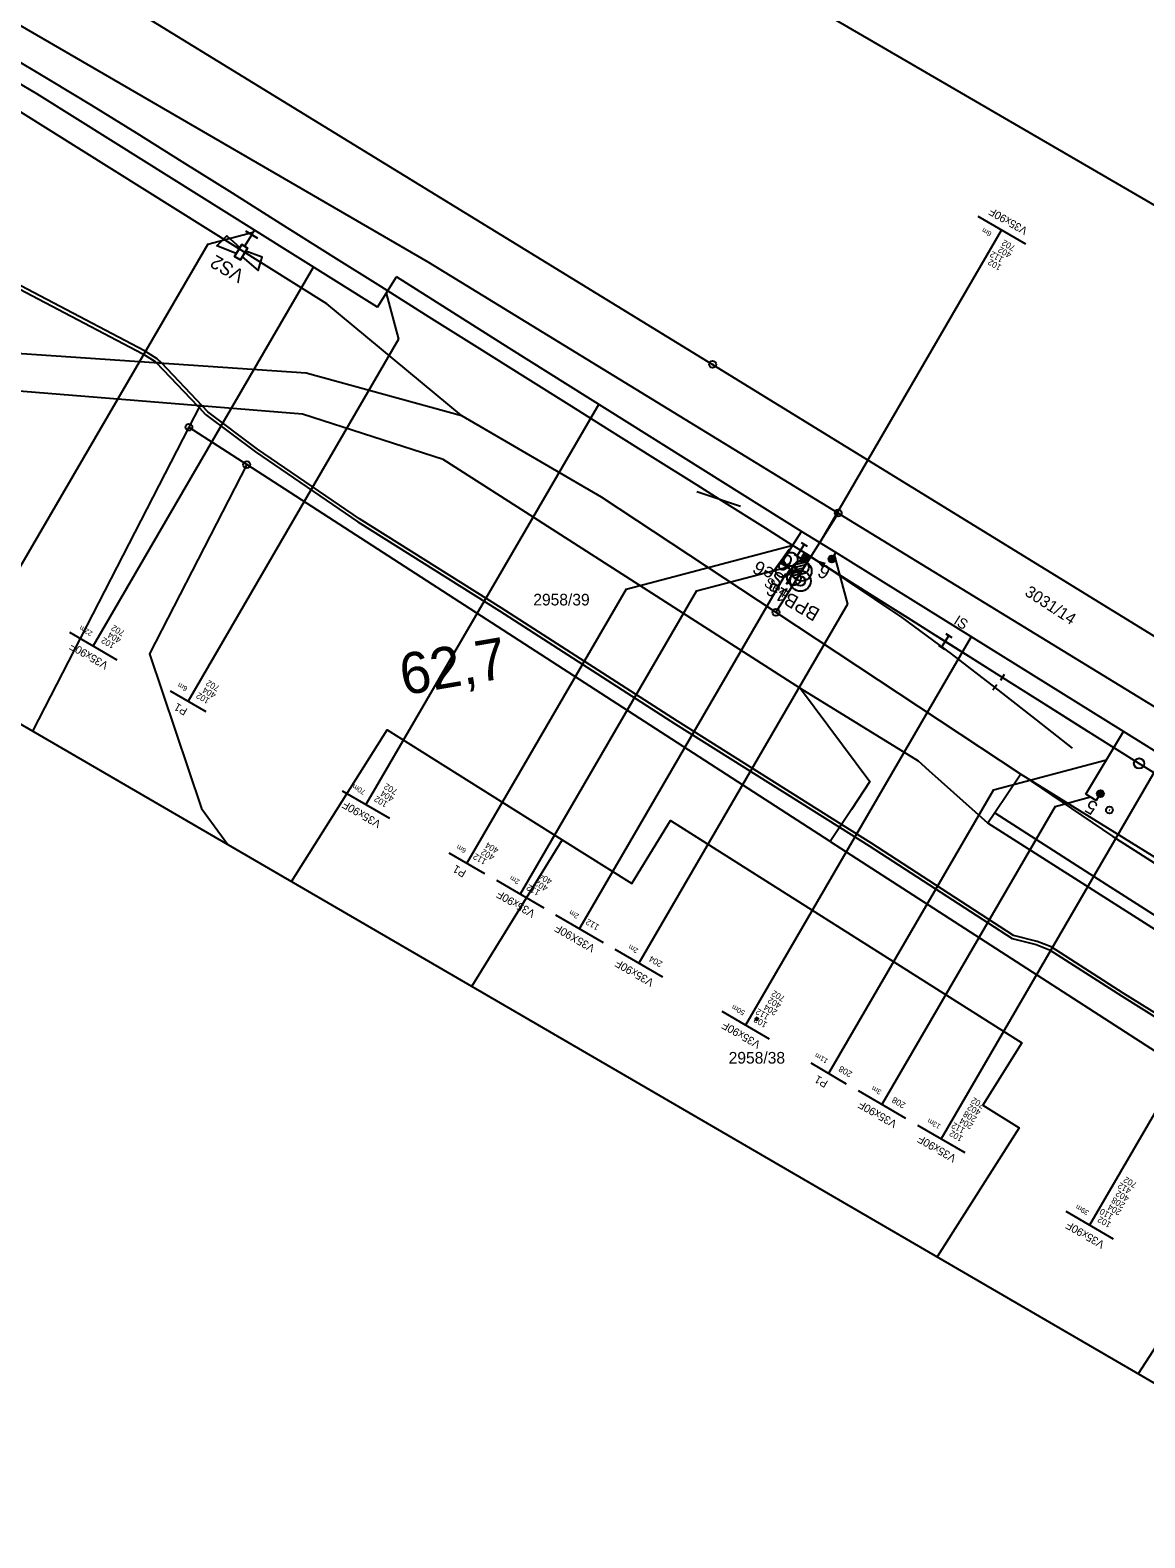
# Model space of a CAD drawing. Extents: x -621126 to -620688, y -1122470 to -1122131.
# Drawn here: x -620965.5 to -620803, y -1122470.1 to -1122250.2 of the extents above; entities that cross this region are included whole.
import ezdxf

# ---------------------------------------------------------------- set-up
doc = ezdxf.new("R2010")
doc.units = 0
for name, color, linetype in [('hm', 7, 'Continuous'), ('HranDP', 7, 'Continuous'), ('Hranice parcel', 7, 'Continuous'), ('Parcelní čísla', 7, 'Continuous'), ('Rámečky-tisk', 7, 'Continuous'), ('STANICENI NOVE HM', 7, 'Continuous'), ('Vnitřní kresba', 7, 'Continuous'), ('Vrstva 1', 7, 'Continuous'), ('Vrstva 2', 7, 'Continuous'), ('Vrstva 3', 7, 'Continuous'), ('Vrstva 33', 7, 'Continuous'), ('Vrstva 6', 7, 'Continuous'), ('Vrstva 7', 7, 'Continuous'), ('Věcná břemena k části', 7, 'Continuous'), ('Značky bodu BP', 7, 'Continuous'), ('Značky budov', 7, 'Continuous')]:
    doc.layers.add(name, color=color, linetype=linetype)

msp = doc.modelspace()

# ---------------------------------------------------------------- linework, layer by layer
at = {"layer": 'hm'}
for p, q in [((-620963.63, -1122256.97), (-620963.63, -1122256.97)), ((-620879.03, -1122309.95), (-620879.03, -1122309.95))]:
    msp.add_line(p, q, dxfattribs=at)
at = {"layer": 'HranDP'}
msp.add_line((-620856.79, -1122335.14), (-620821.12, -1122358.76), dxfattribs=at)
for points in [[(-620902.62, -1122306.44), (-620922.25, -1122290.14), (-620980.18, -1122253.91), (-621018.36, -1122232.1), (-621052.69, -1122216.23), (-621091.75, -1122200.22)], [(-620847.72, -1122320.67), (-620907.48, -1122284.08), (-620974.87, -1122244.96), (-620982.44, -1122240.65)], [(-620902.62, -1122306.44), (-620882.26, -1122318.28), (-620856.79, -1122335.14)], [(-620847.72, -1122320.67), (-620838.83, -1122326.12), (-620768.63, -1122369.09), (-620748.53, -1122378.52), (-620719.75, -1122396)], [(-620821.12, -1122358.76), (-620741.46, -1122408.09), (-620730.75, -1122414.92)]]:
    msp.add_lwpolyline(points, dxfattribs=at)
at = {"layer": 'Hranice parcel'}
for p, q in [((-620976.86, -1122231), (-620866.03, -1122298.98)), ((-620866.03, -1122298.98), (-620716.77, -1122390.88)), ((-620940.78, -1122305.04), (-620942.38, -1122308.15)), ((-620942.38, -1122308.15), (-620965.18, -1122352.45)), ((-620942.38, -1122308.15), (-620933.94, -1122313.6)), ((-620848.87, -1122368.55), (-620933.94, -1122313.6)), ((-620853.22, -1122346.25), (-620894.54, -1122319.77)), ((-620847.72, -1122320.67), (-620856.79, -1122335.14)), ((-620856.79, -1122335.14), (-620821.12, -1122358.76))]:
    msp.add_line(p, q, dxfattribs=at)
for points in [[(-620902.62, -1122306.44), (-620922.25, -1122290.14), (-620980.18, -1122253.91), (-621018.36, -1122232.1), (-621052.69, -1122216.23), (-621091.75, -1122200.22)], [(-620847.72, -1122320.67), (-620907.48, -1122284.08), (-620974.87, -1122244.96), (-620982.44, -1122240.65)], [(-621115.61, -1122241.25), (-621038.08, -1122280.28), (-621008.67, -1122291.25), (-620981.77, -1122296.39), (-620925.27, -1122300.21), (-620902.62, -1122306.44)], [(-620940.78, -1122305.04), (-620976.17, -1122302.17), (-620982.88, -1122301.63), (-621009.79, -1122296.2), (-621017.3, -1122293.74)], [(-620894.54, -1122319.77), (-620905.33, -1122312.86), (-620925.79, -1122306.26), (-620940.78, -1122305.04)], [(-620902.62, -1122306.44), (-620882.26, -1122318.28), (-620856.79, -1122335.14)], [(-620933.94, -1122313.6), (-620948.13, -1122341.18), (-620940.52, -1122363.74), (-620936.7, -1122369.01)], [(-620847.72, -1122320.67), (-620838.83, -1122326.12), (-620768.63, -1122369.09), (-620748.53, -1122378.52), (-620719.75, -1122396)], [(-620825.92, -1122365.89), (-620834.44, -1122358.28), (-620836.04, -1122356.85), (-620853.22, -1122346.25)], [(-620853.22, -1122346.25), (-620843.09, -1122359.81), (-620845.8, -1122363.88), (-620848.5, -1122367.99), (-620848.87, -1122368.55)], [(-620927.44, -1122374.39), (-620913.46, -1122352.29), (-620887.98, -1122368.3), (-620877.81, -1122374.71), (-620872.17, -1122365.51), (-620820.94, -1122397.9), (-620826.62, -1122407), (-620821.36, -1122410.31), (-620833.31, -1122429.13)], [(-620821.12, -1122358.76), (-620824.91, -1122364.39), (-620825.92, -1122365.89)], [(-620821.12, -1122358.76), (-620741.46, -1122408.09), (-620730.75, -1122414.92)], [(-620821.12, -1122358.76), (-620807.67, -1122367.84), (-620731.57, -1122416.33)], [(-620735.65, -1122423.34), (-620825.92, -1122365.89)], [(-620848.87, -1122368.55), (-620781.81, -1122411.87), (-620803.98, -1122446.19)]]:
    msp.add_lwpolyline(points, dxfattribs=at)
at = {"layer": 'Rámečky-tisk'}
for points in [[(-621051.28, -1122130.61), (-621125.92, -1122258.99), (-620762.84, -1122470.11)], [(-620762.84, -1122470.11), (-620688.19, -1122341.73), (-621051.28, -1122130.61)]]:
    msp.add_lwpolyline(points, dxfattribs=at)
at = {"layer": 'Vnitřní kresba'}
for p, q in [((-620824.91, -1122364.39), (-620810.36, -1122373.73)), ((-620887.98, -1122368.3), (-620901.15, -1122389.68)), ((-620810.36, -1122373.73), (-620734.88, -1122422.02))]:
    msp.add_line(p, q, dxfattribs=at)
at = {"layer": 'Vrstva 1'}
for p, q in [((-620933.22, -1122280.07), (-620932.81, -1122279.39)), ((-620914.88, -1122290.62), (-620932.81, -1122279.39)), ((-620914.88, -1122290.62), (-620912.11, -1122286.23)), ((-620856.02, -1122328.01), (-620853.07, -1122323.34)), ((-620848.09, -1122326.43), (-620853.07, -1122323.34)), ((-620806.11, -1122352.53), (-620848.09, -1122326.43)), ((-620856.02, -1122328.01), (-620854.72, -1122328.89)), ((-620811.62, -1122361.65), (-620806.11, -1122352.53))]:
    msp.add_line(p, q, dxfattribs=at)
for points in [[(-620932.81, -1122279.39), (-620953.35, -1122266.52), (-620964.54, -1122259.53), (-620979.4, -1122250.79), (-620982.11, -1122249.22), (-620983.24, -1122251.5), (-620999.51, -1122242.21), (-621017.63, -1122231.73), (-621018.87, -1122231.17), (-621038.19, -1122222.46)], [(-620969.11, -1122253.64), (-620962.44, -1122257.63), (-620956.58, -1122261.19), (-620949.96, -1122265.28), (-620943.39, -1122269.38), (-620936.05, -1122273.98), (-620929.02, -1122278.42), (-620921.28, -1122283.3), (-620914.45, -1122287.58), (-620907.38, -1122292.04), (-620900.38, -1122296.43), (-620893.37, -1122300.83), (-620887.01, -1122304.84), (-620881.07, -1122308.56), (-620874.8, -1122312.5), (-620868.33, -1122316.57), (-620865.13, -1122318.58), (-620858.38, -1122322.84), (-620854.48, -1122325.28), (-620853.21, -1122326.08), (-620851.73, -1122327.01), (-620850.55, -1122327.76), (-620840.58, -1122334.05), (-620833.63, -1122338.43), (-620832.14, -1122339.37), (-620823.78, -1122344.63), (-620817.74, -1122348.46), (-620811.37, -1122352.45)], [(-620853.07, -1122323.34), (-620895.69, -1122296.63), (-620912.11, -1122286.23)], [(-620848.09, -1122326.43), (-620848.09, -1122326.43), (-620848.63, -1122327.36)], [(-620851.64, -1122327.08), (-620843.14, -1122332.43), (-620837.63, -1122335.92), (-620832.12, -1122339.39), (-620828.02, -1122341.97), (-620823.79, -1122344.63), (-620816.97, -1122348.94), (-620810.35, -1122353.09), (-620803.86, -1122357.18), (-620803.36, -1122357.5), (-620800.13, -1122359.53), (-620798.65, -1122360.46), (-620794.42, -1122363.12), (-620788.1, -1122367.1), (-620781.12, -1122371.5), (-620774.17, -1122375.88), (-620767.51, -1122380.06), (-620763.22, -1122382.76), (-620756.39, -1122387.05), (-620748.87, -1122391.78), (-620741.59, -1122396.35), (-620734.61, -1122400.75), (-620727.79, -1122405.03), (-620725.75, -1122406.32)], [(-620850.55, -1122327.76), (-620838.47, -1122335.9), (-620831.26, -1122341.18), (-620824.88, -1122346.1), (-620819.56, -1122350.3), (-620813.61, -1122354.97)], [(-620854.72, -1122328.89), (-620855.09, -1122329.44), (-620854.51, -1122329.81)], [(-620795.27, -1122359.26), (-620795.68, -1122359.01), (-620806.11, -1122352.53)], [(-620809.51, -1122361.58), (-620810.11, -1122362.57), (-620811.62, -1122361.65)]]:
    msp.add_lwpolyline(points, dxfattribs=at)
at = {"layer": 'Vrstva 2'}
for p, q in [((-620934.25, -1122281.78), (-620933.22, -1122280.07)), ((-620934.25, -1122281.78), (-620933.22, -1122280.07)), ((-620932.37, -1122280.58), (-620934.08, -1122279.55)), ((-620934.08, -1122279.55), (-620932.37, -1122280.58)), ((-620853.74, -1122328.53), (-620855.29, -1122331.09)), ((-620852.5, -1122328.24), (-620854.45, -1122328.69)), ((-620852.38, -1122327.83), (-620854.23, -1122328.25)), ((-620852.28, -1122327.88), (-620853.83, -1122330.36)), ((-620853.2, -1122327.4), (-620851.84, -1122327.07)), ((-620853.13, -1122327.52), (-620851.85, -1122327.21)), ((-620853.1, -1122327.25), (-620852, -1122326.97)), ((-620853.01, -1122327.09), (-620852.16, -1122326.88)), ((-620852.97, -1122327.62), (-620851.95, -1122327.37)), ((-620852.91, -1122326.93), (-620852.32, -1122326.78)), ((-620852.82, -1122326.77), (-620852.48, -1122326.69)), ((-620852.81, -1122327.71), (-620852.05, -1122327.52)), ((-620852.72, -1122326.61), (-620852.64, -1122326.59)), ((-620852.65, -1122327.81), (-620852.14, -1122327.68)), ((-620852.49, -1122327.91), (-620852.24, -1122327.84)), ((-620852.28, -1122327.88), (-620851.73, -1122327.01)), ((-620852.28, -1122327.88), (-620852.28, -1122327.88)), ((-620848.14, -1122327.31), (-620849.13, -1122327.42)), ((-620848.2, -1122327.11), (-620849.11, -1122327.21)), ((-620848.16, -1122327.51), (-620849.07, -1122327.61)), ((-620848.38, -1122326.93), (-620848.97, -1122327)), ((-620848.29, -1122327.73), (-620848.88, -1122327.79)), ((-620852.78, -1122328.69), (-620854.51, -1122329.09)), ((-620853.07, -1122329.14), (-620854.47, -1122329.46)), ((-620853.35, -1122329.59), (-620854.34, -1122329.82)), ((-620853.63, -1122330.04), (-620854.09, -1122330.15)), ((-620824.58, -1122345.71), (-620825.19, -1122346.5)), ((-620823.51, -1122344.21), (-620824.04, -1122345.06)), ((-620809.97, -1122361.38), (-620809.83, -1122361.96)), ((-620809.82, -1122361.18), (-620809.6, -1122362.07)), ((-620809.63, -1122361.09), (-620809.39, -1122362.06)), ((-620809.43, -1122361.09), (-620809.21, -1122361.97)), ((-620809.2, -1122361.19), (-620809.05, -1122361.77))]:
    msp.add_line(p, q, dxfattribs=at)
for points in [[(-620935.46, -1122282.8), (-620938.28, -1122281.68), (-620936.82, -1122280.23), (-620934.94, -1122281.95)], [(-620934.86, -1122283.75), (-620935.72, -1122283.23), (-620934.68, -1122281.52), (-620933.83, -1122282.04)], [(-620935.72, -1122283.23), (-620934.86, -1122283.75), (-620933.83, -1122282.04), (-620934.68, -1122281.52)], [(-620934.6, -1122283.32), (-620932.29, -1122285.3), (-620931.69, -1122283.33), (-620934.08, -1122282.46)], [(-620852.69, -1122326.56), (-620851.79, -1122327.1), (-620852.33, -1122328), (-620853.23, -1122327.46)], [(-620852.69, -1122326.56), (-620851.79, -1122327.1), (-620852.33, -1122328), (-620853.23, -1122327.46)]]:
    msp.add_lwpolyline(points, close=True, dxfattribs=at)
msp.add_lwpolyline([(-620849.6, -1122328.08), (-620850.55, -1122327.76), (-620849.89, -1122328.51)], dxfattribs=at)
for centre, radius in [((-620853.06, -1122329.13), 1.46), ((-620848.63, -1122327.36), 0.5), ((-620853.23, -1122330.58), 1.5), ((-620853.23, -1122330.58), 0.7), ((-620809.51, -1122361.58), 0.5)]:
    msp.add_circle(centre, radius, dxfattribs=at)
msp.add_arc((-620853.05, -1122329.12), 1.46, 57.9828, 237.9436, dxfattribs=at)
at = {"layer": 'Vrstva 3'}
for p, q in [((-620868.31, -1122317.51), (-620861.96, -1122319.66)), ((-620852.68, -1122325.24), (-620853.74, -1122326.93)), ((-620853.1, -1122324.97), (-620852.25, -1122325.5)), ((-620854.16, -1122326.67), (-620853.32, -1122327.2)), ((-620831.61, -1122338.52), (-620832.67, -1122340.21)), ((-620831.58, -1122338.54), (-620832.65, -1122340.24)), ((-620832.03, -1122338.25), (-620831.18, -1122338.79)), ((-620832.01, -1122338.28), (-620831.16, -1122338.81)), ((-620833.1, -1122339.95), (-620832.25, -1122340.48)), ((-620833.07, -1122339.97), (-620832.22, -1122340.5))]:
    msp.add_line(p, q, dxfattribs=at)
at = {"layer": 'Vrstva 33'}
for p, q in [((-620827.36, -1122277.38), (-620820.44, -1122281.4)), ((-620939.61, -1122281.44), (-620932.99, -1122279.69)), ((-620850.42, -1122324.99), (-620823.9, -1122279.39)), ((-620939.61, -1122281.44), (-620969.3, -1122332.5)), ((-620924.2, -1122284.78), (-620956.33, -1122340.04)), ((-620913.61, -1122288.6), (-620911.83, -1122295.33)), ((-620911.83, -1122295.33), (-620942.5, -1122348.08)), ((-620882.64, -1122304.81), (-620916.57, -1122363.16)), ((-620878.65, -1122331.77), (-620854.32, -1122325.33)), ((-620868.39, -1122332.03), (-620855.22, -1122328.55)), ((-620848.29, -1122326.76), (-620846.38, -1122333.97)), ((-620855.41, -1122329.6), (-620885.45, -1122381.26)), ((-620855.41, -1122329.6), (-620855.01, -1122329.5)), ((-620878.65, -1122331.77), (-620901.87, -1122371.71)), ((-620868.39, -1122332.03), (-620894.09, -1122376.23)), ((-620846.38, -1122333.97), (-620876.8, -1122386.29)), ((-620959.79, -1122338.03), (-620952.88, -1122342.05)), ((-620828.32, -1122338.72), (-620861.24, -1122395.33)), ((-620945.1, -1122346.58), (-620939.91, -1122349.59)), ((-620800.28, -1122356.14), (-620832.72, -1122411.92)), ((-620825.1, -1122361.03), (-620808.6, -1122356.67)), ((-620920.03, -1122361.15), (-620913.11, -1122365.17)), ((-620825.1, -1122361.03), (-620849.14, -1122402.37)), ((-620816.09, -1122363.44), (-620841.36, -1122406.9)), ((-620816.09, -1122363.44), (-620810.93, -1122362.07)), ((-620904.47, -1122370.2), (-620899.28, -1122373.22)), ((-620779.04, -1122369.35), (-620811.1, -1122424.49)), ((-620897.55, -1122374.22), (-620890.63, -1122378.24)), ((-620888.91, -1122379.25), (-620881.99, -1122383.27)), ((-620880.26, -1122384.28), (-620873.34, -1122388.3)), ((-620864.7, -1122393.32), (-620857.78, -1122397.34)), ((-620851.73, -1122400.86), (-620846.55, -1122403.88)), ((-620844.82, -1122404.88), (-620837.9, -1122408.91)), ((-620836.18, -1122409.91), (-620829.26, -1122413.93)), ((-620814.56, -1122422.48), (-620807.64, -1122426.5))]:
    msp.add_line(p, q, dxfattribs=at)
at = {"layer": 'Vrstva 6'}
for p, q in [((-620854.88, -1122326), (-620856.04, -1122327.63)), ((-620856.04, -1122327.63), (-620857.21, -1122329.26))]:
    msp.add_line(p, q, dxfattribs=at)
for centre in [(-620854.65, -1122327.4), (-620855.81, -1122329.03), (-620853.02, -1122328.56), (-620854.18, -1122330.19)]:
    msp.add_ellipse(centre, major_axis=(0.814, -0.582), ratio=0.999505, dxfattribs=at)
at = {"layer": 'Vrstva 7'}
msp.add_line((-620808.23, -1122363.94), (-620808.14, -1122363.99), dxfattribs=at)
for centre, radius in [((-620803.86, -1122357.18), 0.75), ((-620808.18, -1122363.97), 0.5)]:
    msp.add_circle(centre, radius, dxfattribs=at)
at = {"layer": 'Věcná břemena k části'}
for points in [[(-621104.33, -1122221.85), (-621094.36, -1122225.8), (-621066.48, -1122237.54), (-621033.9, -1122251.82), (-621004.33, -1122267.35), (-620977.59, -1122282.48), (-620949.07, -1122297.45), (-620947.3, -1122298.56), (-620947.13, -1122298.73), (-620946.39, -1122298.78), (-620946.98, -1122298.16), (-620948.83, -1122297.01), (-620977.35, -1122282.04), (-621004.09, -1122266.91), (-621033.68, -1122251.36), (-621066.28, -1122237.08), (-621094.18, -1122225.34), (-621104.08, -1122221.42)], [(-620794.67, -1122397.82), (-620806.18, -1122390.67), (-620816.7, -1122383.9), (-620818.72, -1122383.12), (-620822.15, -1122382.27), (-620842.97, -1122368.76), (-620847.24, -1122366.07), (-620847.51, -1122366.48), (-620843.23, -1122369.18), (-620822.35, -1122382.73), (-620818.88, -1122383.6), (-620816.92, -1122384.34), (-620806.44, -1122391.09), (-620794.95, -1122398.24)]]:
    msp.add_lwpolyline(points, dxfattribs=at)
for points in [[(-620941.14, -1122305.01), (-620940.4, -1122305.07), (-620946.39, -1122298.78), (-620947.13, -1122298.73)], [(-620940.9, -1122305.27), (-620939.94, -1122306.28), (-620932.68, -1122311.73), (-620917.76, -1122321.94), (-620897.11, -1122334.91), (-620871.42, -1122351.43), (-620847.51, -1122366.48), (-620847.24, -1122366.07), (-620871.16, -1122351.01), (-620896.85, -1122334.49), (-620917.48, -1122321.52), (-620932.38, -1122311.33), (-620939.6, -1122305.9), (-620940.4, -1122305.07), (-620940.78, -1122305.04)]]:
    msp.add_lwpolyline(points, close=True, dxfattribs=at)
at = {"layer": 'Značky bodu BP'}
for centre, radius in [((-620866.03, -1122298.98), 0.5), ((-620866.03, -1122298.98), 0.0303), ((-620942.38, -1122308.15), 0.5), ((-620942.38, -1122308.15), 0.0303), ((-620933.94, -1122313.6), 0.5), ((-620933.94, -1122313.6), 0.0303), ((-620847.72, -1122320.67), 0.5), ((-620847.72, -1122320.67), 0.0303), ((-620856.79, -1122335.14), 0.5), ((-620856.79, -1122335.14), 0.0303)]:
    msp.add_circle(centre, radius, dxfattribs=at)
at = {"layer": 'Značky budov'}
msp.add_circle((-620859.61, -1122394.47), 0.175, dxfattribs=at)

# ---------------------------------------------------------------- texts
at = {"layer": 'Parcelní čísla'}
for s, p in [('2958/39', (-620892.17, -1122334.14)), ('2958/38', (-620863.69, -1122400.95))]:
    msp.add_text(s, height=1.7, dxfattribs=at).set_placement(p)
msp.add_text('3031/14', height=1.7, rotation=327, dxfattribs=at).set_placement((-620820.66, -1122332.56))
at = {"layer": 'STANICENI NOVE HM'}
msp.add_text('62,7', height=6, rotation=9.6991, dxfattribs=at).set_placement((-620911.08, -1122347.26))
at = {"layer": 'Vrstva 2'}
msp.add_text('6', height=2.5, rotation=147.9632, dxfattribs=at).set_placement((-620853.99, -1122327.35))
at = {"layer": 'Vrstva 3'}
for s, height, rotation, p in [('VS2', 2, 149.8236, (-620934.1, -1122285.47)), ('Se6', 2, 149.8236, (-620855.28, -1122329.88)), ('6', 2, 149.8236, (-620848.64, -1122328.75)), ('BPB16', 2, 149.8236, (-620850.23, -1122334.81)), ('IS', 1.5, 327.8592, (-620831.01, -1122336.74)), ('5', 2, 148.8786, (-620809.69, -1122363.11))]:
    msp.add_text(s, height=height, rotation=rotation, dxfattribs=at).set_placement(p)
at = {"layer": 'Vrstva 33'}
for s, height, p in [('V35x90F', 1.15, (-620820.01, -1122279.17)), ('6m', 0.75, (-620825.27, -1122279.75)), ('112', 0.9, (-620823.53, -1122283.43)), ('402', 0.9, (-620822.36, -1122282.77)), ('702', 0.9, (-620821.81, -1122281.76)), ('102', 0.9, (-620823.83, -1122284.58)), ('22m', 0.75, (-620956.32, -1122338.03)), ('702', 0.9, (-620951.63, -1122337.92)), ('102', 0.9, (-620953.07, -1122339.74)), ('404', 0.9, (-620952.15, -1122338.95)), ('V35x90F', 1.15, (-620954.02, -1122342.54)), ('6m', 0.75, (-620942.49, -1122346.07)), ('404', 0.9, (-620938.32, -1122346.99)), ('702', 0.9, (-620937.8, -1122345.96)), ('P1', 1.15, (-620942.47, -1122349.26)), ('102', 0.9, (-620939.24, -1122347.78)), ('70m', 0.75, (-620916.55, -1122361.15)), ('404', 0.9, (-620912.38, -1122362.07)), ('702', 0.9, (-620911.86, -1122361.04)), ('V35x90F', 1.15, (-620914.26, -1122365.66)), ('102', 0.9, (-620913.3, -1122362.86)), ('6m', 0.75, (-620901.86, -1122369.69)), ('112', 0.9, (-620898.88, -1122371.25)), ('402', 0.9, (-620897.72, -1122370.6)), ('404', 0.9, (-620897.11, -1122369.62)), ('P1', 1.15, (-620901.84, -1122372.88)), ('2m', 0.75, (-620894.08, -1122374.22)), ('112', 0.9, (-620891.1, -1122375.77)), ('402', 0.9, (-620889.94, -1122375.12)), ('404', 0.9, (-620889.33, -1122374.14)), ('V35x90F', 1.15, (-620891.78, -1122378.73)), ('2m', 0.75, (-620885.43, -1122379.24)), ('V35X90F', 1.15, (-620883.07, -1122383.8)), ('112', 0.9, (-620882.46, -1122380.8)), ('2m', 0.75, (-620876.79, -1122384.27)), ('204', 0.9, (-620873.23, -1122386.17)), ('V35x90F', 1.15, (-620874.49, -1122388.79)), ('50m', 0.75, (-620861.23, -1122393.32)), ('204', 0.9, (-620856.51, -1122393.23)), ('402', 0.9, (-620855.93, -1122392.23)), ('702', 0.9, (-620855.38, -1122391.22)), ('102', 0.9, (-620857.98, -1122395.03)), ('112', 0.9, (-620857.68, -1122393.88)), ('V35x90F', 1.15, (-620858.93, -1122397.83)), ('11m', 0.75, (-620849.12, -1122400.36)), ('P1', 1.15, (-620849.11, -1122403.55)), ('208', 0.9, (-620845.59, -1122402.23)), ('3m', 0.75, (-620841.34, -1122404.88)), ('V35x90F', 1.15, (-620839.05, -1122409.4)), ('208', 0.9, (-620837.81, -1122406.76)), ('402', 0.9, (-620826.83, -1122407.82)), ('702', 0.9, (-620826.28, -1122406.82)), ('13m', 0.75, (-620832.7, -1122409.9)), ('112', 0.9, (-620829.15, -1122410.47)), ('204', 0.9, (-620827.99, -1122409.81)), ('208', 0.9, (-620827.44, -1122408.8)), ('V35x90F', 1.15, (-620830.41, -1122414.42)), ('102', 0.9, (-620829.45, -1122411.62)), ('412', 0.9, (-620804.91, -1122419.24)), ('702', 0.9, (-620804.08, -1122418.39)), ('208', 0.9, (-620805.82, -1122421.37)), ('402', 0.9, (-620805.21, -1122420.39)), ('39m', 0.75, (-620811.09, -1122422.47)), ('110', 0.9, (-620807.55, -1122423.03)), ('204', 0.9, (-620806.37, -1122422.38)), ('V35x90F', 1.15, (-620808.79, -1122426.99)), ('102', 0.9, (-620807.84, -1122424.19))]:
    msp.add_text(s, height=height, rotation=149.8236, dxfattribs=at).set_placement(p)
at = {"layer": 'Vrstva 6'}
msp.add_text('Se4', height=1.5, rotation=327.8625, dxfattribs=at).set_placement((-620858.66, -1122331.2))

doc.saveas('drawing.dxf')
